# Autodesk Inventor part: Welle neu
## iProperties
Created: 2006-11
Part Number: Welle neu
Cost Center: 0,227 kg
Material: Stahl (schweißbar)
Document SubType Name: Modeling
Designer: Schmidt
Authority: 28931 mm^3
Density: 7.86 g/cm^3
SaveDate: 2006-11-05
SaveTime: 22:50
TotalMass: 0,227 kg
TotalVolume: 28931 mm^3
Author: Schmidt
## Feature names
1. Drehung1 [Revolution]
2. Bohrung2 [Hole]
3. Runde Anordnung1 [Circular Pattern]
